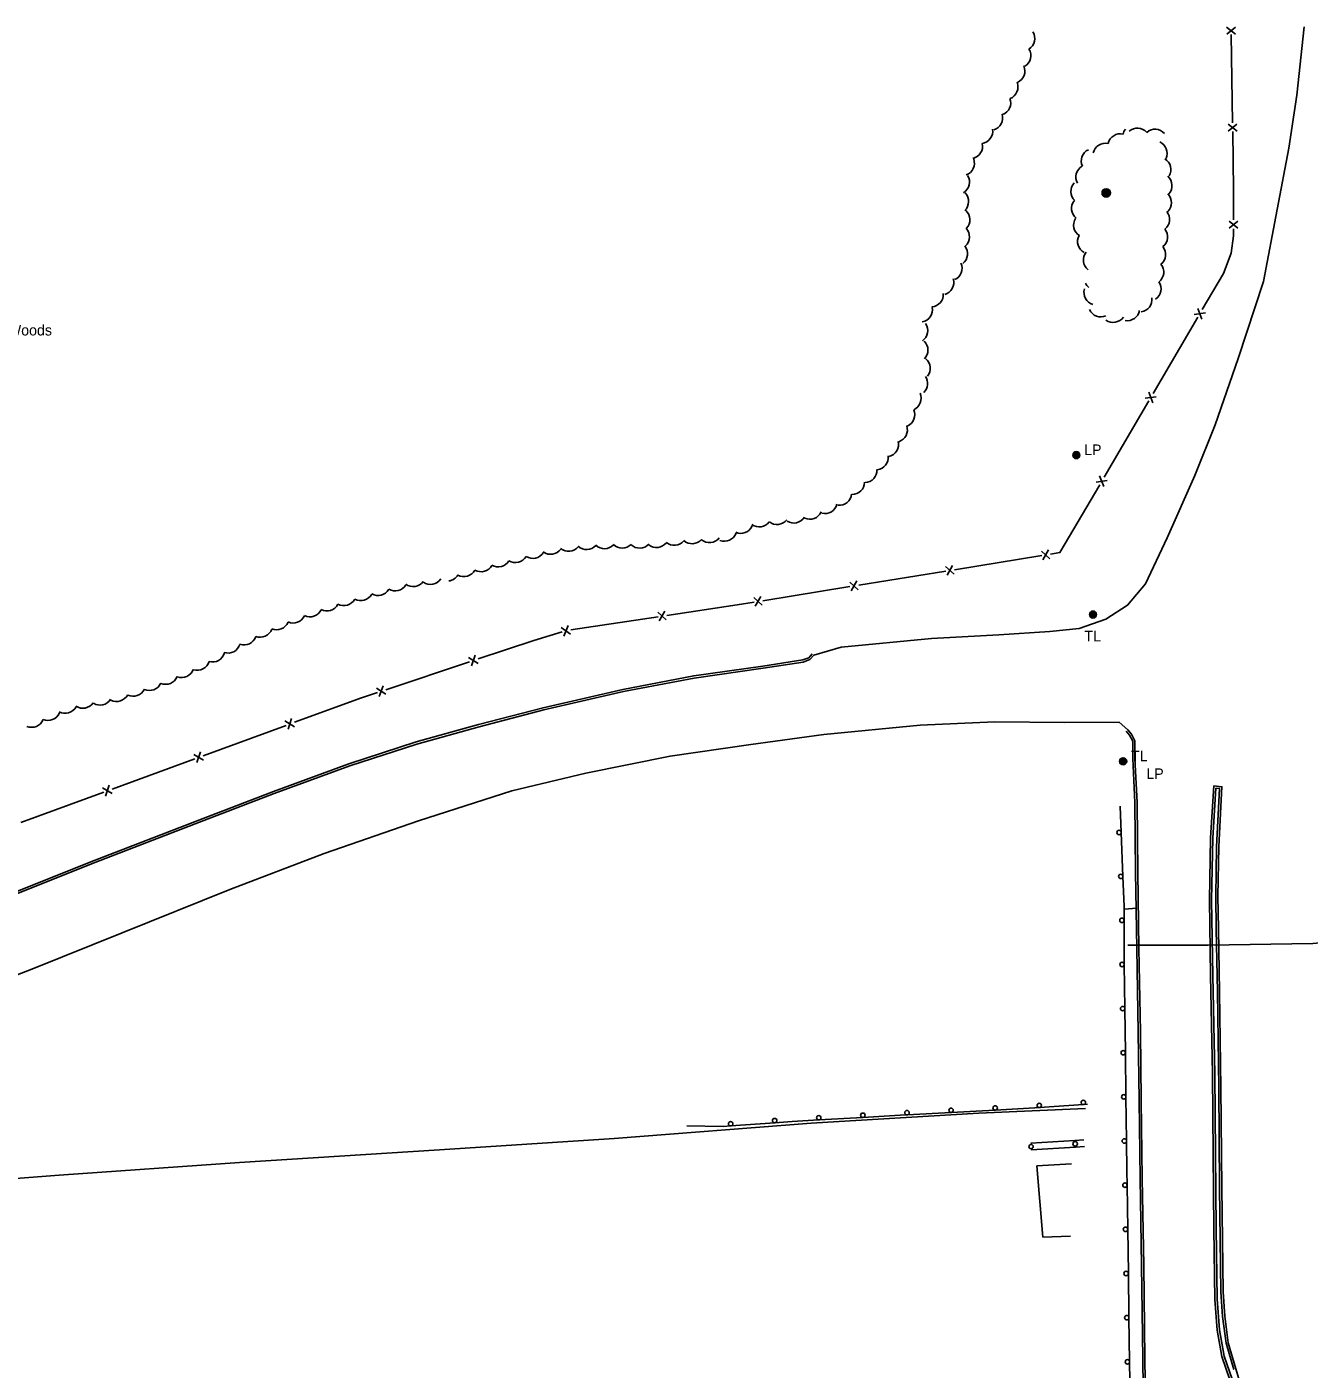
# Model space of a CAD drawing. Extents: x 2402803 to 2427059, y 6985292 to 6997652.
# Drawn here: x 2422158 to 2422739, y 6991483 to 6992091 of the extents above; entities that cross this region are included whole.
import ezdxf

# ---------------------------------------------------------------- set-up
doc = ezdxf.new("R2010")
doc.units = 0
for name, color, linetype in [('p_road - paved curb', 7, 'Continuous'), ('p_road bridge end', 7, 'Continuous'), ('p_road conc barrier', 7, 'Continuous'), ('p_road guard rails', 7, 'Continuous'), ('p_structure fence', 7, 'Continuous'), ('p_structure sidewalk', 7, 'Continuous'), ('p_utility manhole', 7, 'Continuous'), ('p_veg woods', 7, 'Continuous')]:
    doc.layers.add(name, color=color, linetype=linetype)

msp = doc.modelspace()

# ---------------------------------------------------------------- linework, layer by layer
at = {"layer": 'p_road - paved curb'}
for points in [[(2422514.39, 6991806.18), (2422526.9, 6991809.85), (2422567.8, 6991813.69), (2422598.27, 6991815.42), (2422621.37, 6991816.9), (2422634.54, 6991818.32), (2422646.72, 6991822.52), (2422656.51, 6991828.79), (2422664.67, 6991838.52), (2422674.52, 6991859.35), (2422686.97, 6991887.51), (2422696.13, 6991910.5), (2422706.68, 6991940.49), (2422718.1, 6991975.42), (2422724.22, 6992008.01), (2422729.59, 6992035.78), (2422733.24, 6992059.7), (2422736.53, 6992090.63)], [(2422145.86, 6991696.19), (2422187.04, 6991712.72), (2422237.91, 6991732.23), (2422269.7, 6991744.51), (2422303.96, 6991757.03), (2422334.34, 6991766.91), (2422362.65, 6991774.8), (2422391.88, 6991782.38), (2422428.02, 6991790.73), (2422460.11, 6991796.86), (2422491.41, 6991801.27), (2422509.41, 6991804.05), (2422512.13, 6991805.05), (2422513.63, 6991806.82)], [(2422146.23, 6991695.26), (2422187.41, 6991711.79), (2422238.27, 6991731.3), (2422270.05, 6991743.57), (2422304.29, 6991756.08), (2422334.63, 6991765.95), (2422362.91, 6991773.83), (2422392.12, 6991781.41), (2422428.23, 6991789.75), (2422460.27, 6991795.87), (2422491.56, 6991800.28), (2422509.66, 6991803.08), (2422512.72, 6991804.2), (2422514.39, 6991806.18)], [(2422656.59, 6991772.4), (2422652.7, 6991775.85), (2422628.02, 6991775.77), (2422596.4, 6991775.99), (2422562.62, 6991774.57), (2422519.01, 6991770.24), (2422485.89, 6991765.82), (2422449.38, 6991760.51), (2422411.15, 6991752.77), (2422377.65, 6991744.75), (2422335.49, 6991731.23), (2422292.75, 6991716.43), (2422250, 6991700.1), (2422201.29, 6991680.46), (2422161.09, 6991664.4), (2422120.23, 6991648.47)], [(2422660.37, 6991231.35), (2422664.65, 6991234.18), (2422666.79, 6991237.76), (2422666.35, 6991267.89), (2422666.08, 6991297.42), (2422665.81, 6991339.05), (2422664.87, 6991375.29), (2422664.52, 6991407.41), (2422663.94, 6991447.31), (2422663.4, 6991487.9), (2422662.9, 6991529.87), (2422662.16, 6991569.29), (2422661.76, 6991604.55), (2422661.39, 6991635.63), (2422660.68, 6991673.4), (2422660.1, 6991708.01), (2422659.81, 6991739.54), (2422658.86, 6991759.41), (2422658.88, 6991767.24), (2422657.43, 6991769.93), (2422655.84, 6991771.74)], [(2422660.92, 6991230.52), (2422665.39, 6991233.47), (2422667.79, 6991237.49), (2422667.35, 6991267.9), (2422667.08, 6991297.43), (2422666.81, 6991339.07), (2422665.87, 6991375.31), (2422665.52, 6991407.42), (2422664.94, 6991447.32), (2422664.4, 6991487.91), (2422663.9, 6991529.89), (2422663.16, 6991569.31), (2422662.76, 6991604.56), (2422662.39, 6991635.65), (2422661.68, 6991673.42), (2422661.1, 6991708.02), (2422660.81, 6991739.57), (2422659.86, 6991759.43), (2422659.88, 6991767.49), (2422658.26, 6991770.5), (2422656.59, 6991772.4)], [(2422699.2, 6991565.21), (2422698.82, 6991610.43), (2422698.19, 6991653.85), (2422697.69, 6991682.27), (2422697.47, 6991697.1), (2422697.83, 6991719.38), (2422699.26, 6991746.67), (2422695.63, 6991747.06), (2422694.1, 6991723.46), (2422693.58, 6991695.36), (2422694.09, 6991661.15), (2422695.04, 6991616.72), (2422695.31, 6991580.35), (2422695.63, 6991546.62)], [(2422698.2, 6991565.2), (2422697.82, 6991610.42), (2422697.19, 6991653.83), (2422696.69, 6991682.25), (2422696.47, 6991697.1), (2422696.83, 6991719.41), (2422698.21, 6991745.78), (2422696.56, 6991745.95), (2422695.1, 6991723.42), (2422694.58, 6991695.36), (2422695.09, 6991661.17), (2422696.04, 6991616.73), (2422696.31, 6991580.36), (2422696.63, 6991546.63)], [(2421730.18, 6991538.22), (2421783.91, 6991541.31), (2421842.98, 6991546.36), (2421906.64, 6991551.54), (2421964.04, 6991555.35), (2422029.05, 6991560.34), (2422096.32, 6991565.01), (2422172.66, 6991570.84), (2422254.42, 6991576.57), (2422344.93, 6991582.24), (2422424.07, 6991587.49), (2422513.29, 6991594.29), (2422589.21, 6991598.92), (2422637.47, 6991601.07)], [(2422631.15, 6991575.92), (2422615.49, 6991574.99), (2422618.2, 6991542.82), (2422630.71, 6991543.14)], [(2422704.66, 6991482.82), (2422701.17, 6991494.75), (2422699.51, 6991506.9), (2422698.78, 6991518), (2422698.2, 6991565.2)], [(2422708.71, 6991472.53), (2422705.62, 6991483.1), (2422702.15, 6991494.96), (2422700.51, 6991507), (2422699.78, 6991518.04), (2422699.2, 6991565.21)], [(2422695.63, 6991546.62), (2422696.09, 6991514.57), (2422697.17, 6991500.68), (2422699.25, 6991488.71), (2422702.89, 6991478.13)], [(2422696.63, 6991546.63), (2422697.09, 6991514.62), (2422698.16, 6991500.8), (2422700.22, 6991488.96), (2422703.84, 6991478.43)]]:
    msp.add_lwpolyline(points, dxfattribs=at)
at = {"layer": 'p_road bridge end'}
msp.add_lwpolyline([(2422656.67, 6991674.91), (2422662.74, 6991674.96), (2422693.08, 6991674.98), (2422740.35, 6991675.74), (2422742.08, 6991675.79), (2422747.12, 6991676.1)], dxfattribs=at)
at = {"layer": 'p_road conc barrier'}
for p, q in [((2422612.75, 6991585.25), (2422632.71, 6991586.5)), ((2422632.71, 6991586.5), (2422636.79, 6991586.76)), ((2422612.94, 6991582.25), (2422632.9, 6991583.51)), ((2422632.9, 6991583.51), (2422636.98, 6991583.76))]:
    msp.add_line(p, q, dxfattribs=at)
for centre in [(2422632.8, 6991585), (2422612.84, 6991583.75)]:
    msp.add_circle(centre, 1, dxfattribs=at)
at = {"layer": 'p_road guard rails'}
for p, q in [((2422653.68, 6991725.97), (2422653.24, 6991737.93)), ((2422654.42, 6991706.08), (2422653.68, 6991725.97)), ((2422655.3, 6991646.24), (2422655.05, 6991666.21)), ((2422655.56, 6991626.26), (2422655.3, 6991646.24)), ((2422655.81, 6991606.28), (2422655.56, 6991626.26)), ((2422656.07, 6991586.31), (2422655.81, 6991606.28)), ((2422556.69, 6991598.11), (2422576.66, 6991599.19)), ((2422576.66, 6991599.19), (2422596.63, 6991600.27)), ((2422616.6, 6991601.38), (2422636.54, 6991602.76)), ((2422636.54, 6991602.76), (2422638.36, 6991602.89)), ((2422476.85, 6991593.11), (2422496.8, 6991594.55)), ((2422516.76, 6991595.81), (2422536.72, 6991596.97)), ((2422656.6, 6991546.33), (2422656.33, 6991566.33)), ((2422656.88, 6991526.33), (2422656.6, 6991546.33)), ((2422657.44, 6991486.34), (2422657.15, 6991506.34)), ((2422657.72, 6991466.34), (2422657.44, 6991486.34))]:
    msp.add_line(p, q, dxfattribs=at)
for points in [[(2422654.95, 6991686.18), (2422654.93, 6991692.47), (2422654.42, 6991706.08)], [(2422655.05, 6991666.21), (2422655.01, 6991669.06), (2422654.95, 6991686.18)], [(2422536.72, 6991596.97), (2422553.59, 6991597.94), (2422556.69, 6991598.11)], [(2422596.63, 6991600.27), (2422614.58, 6991601.24), (2422616.6, 6991601.38)], [(2422456.9, 6991593.09), (2422473.34, 6991592.86), (2422476.85, 6991593.11)], [(2422496.8, 6991594.55), (2422504.59, 6991595.11), (2422516.76, 6991595.81)], [(2422656.33, 6991566.33), (2422656.24, 6991572.68), (2422656.07, 6991586.31)], [(2422657.15, 6991506.34), (2422657.14, 6991507.1), (2422656.88, 6991526.33)]]:
    msp.add_lwpolyline(points, dxfattribs=at)
for centre in [(2422652.69, 6991725.93), (2422653.42, 6991706.05), (2422653.95, 6991686.17), (2422654.05, 6991666.2), (2422654.3, 6991646.22), (2422654.56, 6991626.25), (2422636.48, 6991603.76), (2422654.81, 6991606.27), (2422536.66, 6991597.96), (2422556.63, 6991599.11), (2422576.6, 6991600.19), (2422596.57, 6991601.27), (2422616.53, 6991602.38), (2422476.78, 6991594.11), (2422496.72, 6991595.55), (2422516.7, 6991596.81), (2422655.07, 6991586.3), (2422655.33, 6991566.31), (2422655.6, 6991546.32), (2422655.88, 6991526.32), (2422656.15, 6991506.32), (2422656.44, 6991486.33)]:
    msp.add_circle(centre, 1, dxfattribs=at)
at = {"layer": 'p_structure fence'}
for p, q in [((2422705.42, 6992087.33), (2422701.37, 6992090.47)), ((2422705.37, 6992090.53), (2422701.42, 6992087.27)), ((2422704.08, 6992047.2), (2422703.46, 6992087.1)), ((2422706.11, 6992043.44), (2422702.06, 6992046.58)), ((2422706.06, 6992046.64), (2422702.11, 6992043.38)), ((2422706.5, 6991999.47), (2422702.5, 6992002.68)), ((2422706.5, 6992002.67), (2422702.5, 6991999.48)), ((2422690.15, 6991958.36), (2422688.32, 6991963.14)), ((2422668.15, 6991924.72), (2422688.35, 6991959.18)), ((2422691.77, 6991961.12), (2422686.7, 6991960.38)), ((2422645.94, 6991886.82), (2422666.14, 6991921.28)), ((2422669.55, 6991923.22), (2422664.48, 6991922.48)), ((2422667.94, 6991920.45), (2422666.1, 6991925.24)), ((2422647.34, 6991885.31), (2422642.27, 6991884.57)), ((2422645.72, 6991882.55), (2422643.89, 6991887.33)), ((2422621.38, 6991849.89), (2422617.58, 6991853.32)), ((2422618.22, 6991849.38), (2422620.74, 6991853.83)), ((2422578.22, 6991844.91), (2422617.71, 6991851.29)), ((2422534.78, 6991837.9), (2422574.27, 6991844.27)), ((2422577.94, 6991842.87), (2422574.14, 6991846.31)), ((2422574.78, 6991842.36), (2422577.3, 6991846.82)), ((2422491.35, 6991830.88), (2422530.83, 6991837.26)), ((2422534.5, 6991835.86), (2422530.71, 6991839.29)), ((2422531.35, 6991835.35), (2422533.87, 6991839.8)), ((2422491.07, 6991828.84), (2422487.27, 6991832.28)), ((2422487.91, 6991828.33), (2422490.43, 6991832.79)), ((2422404.35, 6991817.63), (2422443.9, 6991823.6)), ((2422447.56, 6991822.16), (2422443.8, 6991825.64)), ((2422444.39, 6991821.68), (2422446.96, 6991826.11)), ((2422404.29, 6991815.78), (2422400.08, 6991818.7)), ((2422401.22, 6991814.87), (2422403.15, 6991819.61)), ((2422362.44, 6991802.43), (2422358.14, 6991805.21)), ((2422359.4, 6991801.42), (2422361.17, 6991806.23)), ((2422320.64, 6991790.59), (2422358.59, 6991803.23)), ((2422320.69, 6991788.53), (2422316.39, 6991791.32)), ((2422317.65, 6991787.52), (2422319.43, 6991792.33)), ((2422237.94, 6991760.71), (2422275.48, 6991774.43)), ((2422279.35, 6991773.75), (2422274.97, 6991776.41)), ((2422276.34, 6991772.65), (2422277.97, 6991777.51)), ((2422235.06, 6991757.55), (2422236.69, 6991762.41)), ((2422196.66, 6991745.6), (2422234.19, 6991759.33)), ((2422238.06, 6991758.65), (2422233.68, 6991761.31)), ((2422155.37, 6991730.5), (2422192.91, 6991744.23)), ((2422196.78, 6991743.55), (2422192.4, 6991746.2)), ((2422193.77, 6991742.45), (2422195.4, 6991747.3))]:
    msp.add_line(p, q, dxfattribs=at)
for points in [[(2422704.53, 6992003.27), (2422704.56, 6992016.89), (2422704.15, 6992043.21)], [(2422690.37, 6991962.63), (2422699.93, 6991978.94), (2422703.44, 6991988.11), (2422704.52, 6991996.06), (2422704.53, 6991999.27)], [(2422621.66, 6991851.93), (2422625.89, 6991852.61), (2422643.92, 6991883.37)], [(2422447.86, 6991824.2), (2422479.7, 6991829), (2422487.4, 6991830.24)], [(2422362.38, 6991804.49), (2422387.71, 6991812.92), (2422400.47, 6991816.7)], [(2422279.23, 6991775.81), (2422309.58, 6991786.91), (2422316.84, 6991789.33)]]:
    msp.add_lwpolyline(points, dxfattribs=at)
at = {"layer": 'p_structure sidewalk'}
msp.add_lwpolyline([(2422660.37, 6991691.65), (2422655.35, 6991691.27)], dxfattribs=at)
at = {"layer": 'p_utility manhole'}
for centre, radius in [((2422646.85, 6992015.46), 1.9), ((2422646.85, 6992015.46), 1.44), ((2422646.85, 6992015.46), 0.973), ((2422646.85, 6992015.46), 0.539), ((2422646.85, 6992015.46), 0.192), ((2422633.32, 6991896.78), 1.6), ((2422633.32, 6991896.78), 1.3), ((2422633.32, 6991896.78), 1), ((2422633.32, 6991896.78), 0.539), ((2422633.32, 6991896.78), 0.192), ((2422640.87, 6991824.58), 1.6), ((2422640.87, 6991824.58), 1.3), ((2422640.87, 6991824.58), 1), ((2422640.87, 6991824.58), 0.539), ((2422640.87, 6991824.58), 0.192), ((2422654.53, 6991758.17), 1.6), ((2422654.53, 6991758.17), 1.3), ((2422654.53, 6991758.17), 1), ((2422654.53, 6991758.17), 0.539), ((2422654.53, 6991758.17), 0.192)]:
    msp.add_circle(centre, radius, dxfattribs=at)
at = {"layer": 'p_veg woods'}
for centre, start, end in [((2422608.88, 6992085.36), 301.96079, 31.96079), ((2422607.08, 6992077.56), 301.96079, 31.96079), ((2422604.38, 6992070.64), 293.73042, 23.73042), ((2422601.24, 6992063.42), 291.90196, 21.90196), ((2422597.95, 6992056.24), 290.36703, 20.36703), ((2422594.33, 6992049.33), 287.51571, 17.51571), ((2422589.83, 6992043.49), 278.23134, 8.23134), ((2422653.26, 6992036.59), 77.25569, 167.25569), ((2422660.01, 6992040.85), 142.57098, 167.25569), ((2422660.99, 6992039.13), 41.47855, 131.47855), ((2422668.97, 6992038.64), 41.47855, 131.47855), ((2422585.21, 6992036.6), 282.43234, 12.43234), ((2422646.5, 6992032.32), 77.25569, 167.25569), ((2422668.79, 6992033.37), 335.98237, 65.98237), ((2422581.53, 6992028.91), 289.95229, 19.95229), ((2422641.18, 6992029.9), 114.79024, 204.79024), ((2422670.47, 6992026.04), 328.89234, 58.89234), ((2422638.71, 6992022.66), 119.74275, 209.74275), ((2422579.29, 6992020.36), 301.78377, 31.78377), ((2422636.5, 6992016.07), 136.54917, 226.54917), ((2422671.01, 6992018.74), 318.96065, 48.96065), ((2422578.91, 6992011.57), 313.05584, 43.05584), ((2422636.76, 6992008.48), 142.26281, 232.26281), ((2422670.76, 6992011.05), 314.36129, 44.36129), ((2422579.44, 6992003.25), 317.60906, 47.60906), ((2422669.9, 6992003.5), 308.55201, 38.55201), ((2422579.29, 6991995.55), 313.36224, 43.36224), ((2422637.72, 6992000.91), 147.6555, 237.6555), ((2422639.53, 6991993.42), 151.57659, 241.57659), ((2422669.01, 6991995.55), 308.55201, 38.55201), ((2422578.43, 6991987.95), 308.32536, 38.32536), ((2422642.16, 6991985.07), 141.15733, 231.15733), ((2422668.1, 6991987.61), 308.51486, 38.51486), ((2422575.93, 6991981.39), 293.85299, 23.85299), ((2422667.27, 6991979.62), 308.92985, 38.92985), ((2422572.18, 6991974.86), 286.76423, 16.76423), ((2422666.07, 6991972.05), 304.20932, 34.20932), ((2422567.45, 6991969.45), 274.67253, 4.67253), ((2422642.42, 6991970.38), 163.39345, 253.39345), ((2422642.52, 6991977.06), 206.31109, 230.72631), ((2422562.54, 6991962.63), 280.48451, 10.48451), ((2422661.9, 6991967.16), 278.48814, 8.48814), ((2422644.41, 6991965), 204.45377, 294.45377), ((2422649.99, 6991962.48), 235.0858, 325.0858), ((2422656.4, 6991963.26), 259.66532, 349.66532), ((2422560.42, 6991953.12), 304.50269, 34.50269), ((2422560.48, 6991944.32), 315.52076, 45.52076), ((2422561.55, 6991936), 320.90263, 50.90263), ((2422560.36, 6991929.19), 313.74091, 34.82627), ((2422557.4, 6991922.49), 294.22404, 24.22404), ((2422554.52, 6991915.06), 293.73966, 23.73966), ((2422551.18, 6991908.22), 288.19374, 18.19374), ((2422547.18, 6991901.66), 283.63242, 13.63242), ((2422542.52, 6991895.72), 276.94912, 6.94912), ((2422537.38, 6991889.94), 273.23499, 3.23499), ((2422531.81, 6991884.61), 268.98723, 358.98723), ((2422525.9, 6991879.67), 264.63762, 354.63762), ((2422519.46, 6991875.95), 256.18757, 346.18757), ((2422489.76, 6991869.91), 233.50973, 323.50973), ((2422497.86, 6991871), 231.07072, 321.07072), ((2422505.39, 6991871.68), 237.59852, 327.59852), ((2422512.6, 6991873.38), 246.09587, 336.09587), ((2422473.95, 6991863.44), 249.29218, 339.29218), ((2422481.39, 6991866.99), 245.92843, 335.92843), ((2422395.22, 6991857.51), 234.42342, 324.42342), ((2422403.34, 6991858.85), 231.04263, 321.04263), ((2422411.53, 6991859.67), 227.73846, 317.73846), ((2422419.58, 6991860.06), 226.88038, 316.88038), ((2422427.7, 6991860.33), 225.14233, 315.14233), ((2422435.58, 6991860.31), 226.83548, 316.83547), ((2422443.24, 6991860.61), 231.77006, 321.77006), ((2422451.29, 6991861.62), 230.18416, 320.18416), ((2422459.34, 6991862.31), 228.90153, 318.90153), ((2422467.19, 6991862.82), 230.87534, 320.87534), ((2422371.55, 6991851.79), 239.32888, 329.32888), ((2422379.36, 6991853.8), 238.40889, 328.40889), ((2422387.18, 6991855.66), 237.88232, 327.88232), ((2422348.4, 6991845.4), 277.47136, 329.57314), ((2422356.04, 6991847.43), 240.92034, 330.92034), ((2422363.76, 6991849.63), 240.60086, 330.60086), ((2422317.09, 6991838.85), 239.96397, 329.96397), ((2422324.86, 6991840.94), 239.25206, 329.25206), ((2422333.04, 6991842.9), 233.42369, 323.42369), ((2422340.82, 6991843.92), 235.68216, 325.68216), ((2422293.95, 6991831.88), 242.22701, 332.22701), ((2422301.64, 6991834.28), 241.48711, 331.48711), ((2422309.33, 6991836.56), 241.12826, 331.12826), ((2422278.69, 6991826.38), 245.49224, 335.49224), ((2422286.27, 6991829.23), 244.02249, 334.02249), ((2422263.72, 6991819.98), 249.44033, 339.44033), ((2422271.17, 6991823.34), 247.07216, 337.07216), ((2422249.2, 6991812.81), 252.34694, 342.34694), ((2422256.43, 6991816.5), 250.62977, 340.62977), ((2422242.13, 6991808.77), 254.29904, 344.29904), ((2422228.13, 6991801.69), 249.90909, 339.90909), ((2422235.17, 6991804.99), 253.19659, 343.19659), ((2422213.63, 6991795.87), 245.6994, 335.6994), ((2422220.93, 6991798.66), 247.63205, 337.63205), ((2422198.71, 6991790.86), 242.88341, 332.88341), ((2422206.21, 6991793.26), 244.39142, 334.39142), ((2422175.45, 6991785.56), 240.94457, 330.94457), ((2422183.47, 6991787.83), 236.14311, 326.14311), ((2422191.24, 6991789.24), 237.70413, 327.70413), ((2422160.24, 6991779.21), 247.61223, 337.61223), ((2422167.68, 6991782.34), 246.53865, 336.53865)]:
    msp.add_arc(centre, 5.65, start, end, dxfattribs=at)

# ---------------------------------------------------------------- texts
at = {"layer": 'p_utility manhole'}
for s, p in [('  LP', (2422633.32, 6991896.78)), ('  TL', (2422633.43, 6991812.45)), ('  TL', (2422654.53, 6991758.17)), ('LP', (2422665.05, 6991750.16))]:
    msp.add_text(s, height=4.8, dxfattribs=at).set_placement(p)
at = {"layer": 'p_veg woods'}
msp.add_text('Dense Woods', height=4.8, dxfattribs=at).set_placement((2422129.13, 6991950.92))

doc.saveas('drawing.dxf')
